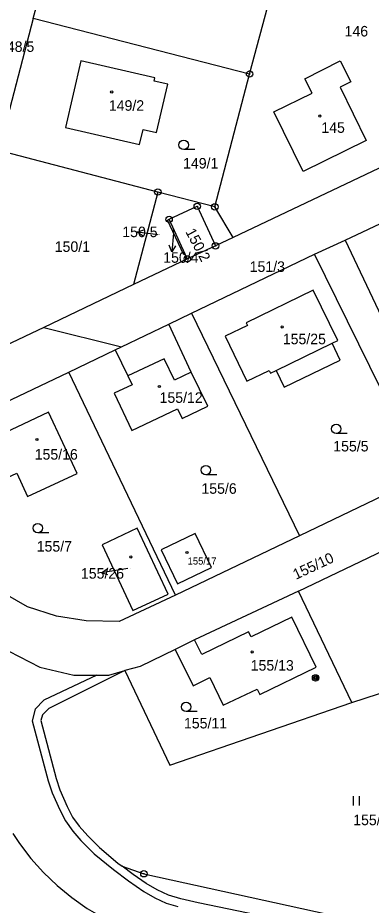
# Model space of a CAD drawing. Extents: x -737240 to -735272, y -1119606 to -1117878.
# Drawn here: x -736818.9 to -736761.9, y -1119214.7 to -1119071.3 of the extents above; entities that cross this region are included whole.
import ezdxf

# ---------------------------------------------------------------- set-up
doc = ezdxf.new("R2010")
doc.units = 0
for name, color, linetype in [('Level 1', 7, 'Continuous'), ('Level 16', 7, 'Continuous'), ('Level 18', 7, 'Continuous'), ('Level 19', 7, 'Continuous'), ('Level 25', 7, 'Continuous'), ('Level 4', 7, 'Continuous')]:
    doc.layers.add(name, color=color, linetype=linetype)

msp = doc.modelspace()

# ---------------------------------------------------------------- linework, layer by layer
at = {"layer": 'Level 1'}
for p, q in [((-736816.39, -1119071.39), (-736810.93, -1119050.62)), ((-736781.48, -1119080.38), (-736775.91, -1119059.43)), ((-736816.39, -1119071.39), (-736822, -1119092.75)), ((-736781.48, -1119080.38), (-736816.39, -1119071.39)), ((-736787.09, -1119101.84), (-736781.48, -1119080.38)), ((-736796.29, -1119099.44), (-736822, -1119092.75)), ((-736757.34, -1119094.04), (-736784.14, -1119106.77)), ((-736796.29, -1119099.44), (-736800.2, -1119114.37)), ((-736787.09, -1119101.84), (-736796.29, -1119099.44)), ((-736784.14, -1119106.77), (-736787.09, -1119101.84)), ((-736766.08, -1119107.23), (-736755.89, -1119102.38)), ((-736791.87, -1119109.47), (-736794.47, -1119103.84)), ((-736784.14, -1119106.77), (-736786.98, -1119108.14)), ((-736771.02, -1119109.49), (-736766.08, -1119107.23)), ((-736786.98, -1119108.14), (-736791.52, -1119110.23)), ((-736791.52, -1119110.23), (-736800.2, -1119114.37)), ((-736791.52, -1119110.23), (-736791.87, -1119109.47)), ((-736790.84, -1119119), (-736771.02, -1119109.49)), ((-736753.41, -1119145.33), (-736771.02, -1119109.49)), ((-736800.2, -1119114.37), (-736814.71, -1119121.3)), ((-736794.53, -1119120.77), (-736790.84, -1119119)), ((-736790.84, -1119119), (-736773.44, -1119154.96)), ((-736814.71, -1119121.3), (-736802.17, -1119124.44)), ((-736802.17, -1119124.44), (-736794.53, -1119120.77)), ((-736790.92, -1119128.54), (-736794.53, -1119120.77)), ((-736803.16, -1119124.91), (-736802.17, -1119124.44)), ((-736810.68, -1119128.52), (-736803.16, -1119124.91)), ((-736803.16, -1119124.91), (-736801.14, -1119129.12)), ((-736830.54, -1119138.05), (-736810.68, -1119128.52)), ((-736793.45, -1119164.56), (-736810.68, -1119128.52)), ((-736753.41, -1119145.33), (-736773.44, -1119154.96)), ((-736773.6, -1119163.92), (-736752.44, -1119153.75)), ((-736773.44, -1119154.96), (-736793.45, -1119164.56)), ((-736773.6, -1119163.92), (-736790.36, -1119171.8)), ((-736764.96, -1119181.9), (-736773.6, -1119163.92)), ((-736790.36, -1119171.8), (-736793.49, -1119173.32)), ((-736764.96, -1119181.9), (-736735.36, -1119172.13))]:
    msp.add_line(p, q, dxfattribs=at)
for points in [[(-736808.72, -1119078.23), (-736811.19, -1119089.04), (-736799.24, -1119091.78), (-736798.67, -1119089.34), (-736796.48, -1119089.85), (-736794.69, -1119082.04), (-736796.89, -1119081.54), (-736796.76, -1119080.97), (-736808.72, -1119078.23)], [(-736772.57, -1119081.15), (-736766.86, -1119078.25), (-736765.15, -1119081.63), (-736766.89, -1119082.5), (-736762.66, -1119091.11), (-736772.86, -1119096.14), (-736777.56, -1119086.49), (-736771.41, -1119083.45), (-736772.57, -1119081.15)], [(-736794.47, -1119103.84), (-736789.93, -1119101.74), (-736786.98, -1119108.14)], [(-736791.87, -1119109.47), (-736792.1, -1119109.58), (-736794.72, -1119104.01), (-736794.47, -1119103.84)], [(-736766.08, -1119107.23), (-736754.84, -1119130.95), (-736746.47, -1119126.97), (-736739.42, -1119123.41), (-736740.88, -1119120.36), (-736741.59, -1119118.86), (-736740.94, -1119118.55), (-736741.1, -1119118.23), (-736743.04, -1119119.15), (-736744.61, -1119115.84)], [(-736768.18, -1119123.88), (-736767.26, -1119123.44), (-736771.23, -1119115.28), (-736782.06, -1119120.55), (-736781.84, -1119121), (-736785.44, -1119122.75), (-736781.92, -1119130), (-736778.33, -1119128.26), (-736778.11, -1119128.71), (-736777.21, -1119128.27)], [(-736814.71, -1119121.3), (-736826.19, -1119126.79), (-736829.11, -1119119.8)], [(-736777.21, -1119128.27), (-736775.88, -1119130.97), (-736766.88, -1119126.58), (-736768.18, -1119123.88)], [(-736801.14, -1119129.12), (-736800.45, -1119130.57), (-736803.35, -1119131.96), (-736800.46, -1119137.97), (-736793.13, -1119134.45), (-736792.37, -1119136.04), (-736788.24, -1119134.06), (-736790.92, -1119128.54)], [(-736813.95, -1119135.03), (-736824.1, -1119139.8), (-736821.24, -1119145.87), (-736819.07, -1119144.88), (-736817.3, -1119148.63), (-736809.3, -1119144.91), (-736813.95, -1119135.03)], [(-736793.45, -1119164.56), (-736802.54, -1119168.8), (-736807.84, -1119168.73), (-736812.66, -1119167.94), (-736817.35, -1119166.45), (-736822.33, -1119163.61), (-736830.54, -1119138.05)], [(-736834.17, -1119146.38), (-736828.05, -1119165.45), (-736824.63, -1119169.96), (-736820.34, -1119173.62), (-736815.31, -1119176.18), (-736809.83, -1119177.49), (-736806.12, -1119177.49)], [(-736805.29, -1119156.42), (-736800.3, -1119167.06), (-736794.61, -1119164.38), (-736799.62, -1119153.76), (-736805.29, -1119156.42)], [(-736793.11, -1119162.73), (-736787.61, -1119160.11), (-736790.24, -1119154.61), (-736795.73, -1119157.24), (-736793.11, -1119162.73)], [(-736793.49, -1119173.32), (-736790.57, -1119179.2), (-736787.89, -1119177.87), (-736785.76, -1119182.34), (-736780.28, -1119179.73), (-736779.85, -1119180.62), (-736770.75, -1119176.22), (-736774.67, -1119168.13), (-736781.25, -1119171.32), (-736781.65, -1119170.49), (-736789.21, -1119174.17), (-736790.36, -1119171.8)], [(-736793.49, -1119173.32), (-736799.15, -1119176.07), (-736801.59, -1119176.75)], [(-736806.12, -1119177.49), (-736814.68, -1119181.53), (-736816.07, -1119182.96), (-736816.58, -1119184.86), (-736814, -1119194.58), (-736813.35, -1119196.48), (-736812.12, -1119199.27), (-736811.19, -1119201.05), (-736810.03, -1119202.71), (-736808.71, -1119204.22), (-736806.57, -1119206.33), (-736803.45, -1119208.91), (-736801.05, -1119210.74), (-736798.54, -1119212.46), (-736796.78, -1119213.47), (-736794.97, -1119214.3), (-736793.05, -1119214.87)], [(-736801.59, -1119176.75), (-736813.89, -1119182.87), (-736814.9, -1119183.88), (-736815.18, -1119184.84), (-736812.71, -1119194.2), (-736812.12, -1119196.03), (-736810.94, -1119198.72), (-736810.05, -1119200.41), (-736809, -1119201.89), (-736807.61, -1119203.44), (-736805.7, -1119205.33), (-736802.73, -1119207.84), (-736802.05, -1119208.36)], [(-736806.12, -1119177.49), (-736804.18, -1119177.49), (-736801.59, -1119176.75)], [(-736801.59, -1119176.75), (-736794.33, -1119192.04), (-736764.96, -1119181.9)], [(-736819.7, -1119203.08), (-736818.63, -1119204.71), (-736816.77, -1119207.12), (-736814.73, -1119209.38), (-736812.53, -1119211.48), (-736810.18, -1119213.41), (-736807.69, -1119215.17), (-736805.07, -1119216.72), (-736802.35, -1119218.08), (-736799.53, -1119219.23), (-736796.64, -1119220.17), (-736793.68, -1119220.89), (-736773.1, -1119225.22)], [(-736802.05, -1119208.36), (-736798.54, -1119209.58), (-736743.15, -1119221.74)], [(-736668.11, -1119254.91), (-736668.26, -1119254.47), (-736670.65, -1119252.61), (-736672.34, -1119251.49), (-736674.09, -1119250.44), (-736675.92, -1119249.53), (-736724.83, -1119229.75), (-736740.44, -1119225.23), (-736766.11, -1119219.16), (-736789.8, -1119214.25), (-736792.59, -1119213.62), (-736794.57, -1119213.03), (-736796.41, -1119212.17), (-736798.16, -1119211.14), (-736800.29, -1119209.7), (-736802.05, -1119208.36)]]:
    msp.add_lwpolyline(points, dxfattribs=at)
at = {"layer": 'Level 16'}
for points in [[(-736798.677, -1119106.562), (-736799.606, -1119105.939), (-736798.55, -1119105.57)], [(-736796.33, -1119106.36), (-736796.63, -1119106.32), (-736799.606, -1119105.939)], [(-736793.91, -1119105.48), (-736793.78, -1119106.09), (-736794.018, -1119109.081)], [(-736793.44, -1119108.123), (-736794.018, -1119109.081), (-736794.437, -1119108.044)], [(-736801.14, -1119160.28), (-736802.44, -1119160.48), (-736805.405, -1119160.936)], [(-736804.341, -1119161.278), (-736805.405, -1119160.936), (-736804.493, -1119160.29)]]:
    msp.add_lwpolyline(points, dxfattribs=at)
at = {"layer": 'Level 25'}
for p, q in [((-736790.338, -1119092.58), (-736792.12, -1119092.58)), ((-736765.718, -1119138.46), (-736767.5, -1119138.46)), ((-736786.758, -1119145.11), (-736788.54, -1119145.11)), ((-736813.878, -1119154.48), (-736815.66, -1119154.48)), ((-736789.948, -1119183.37), (-736791.73, -1119183.37)), ((-736764.787, -1119197.055), (-736764.787, -1119198.555)), ((-736763.765, -1119198.555), (-736763.765, -1119197.055))]:
    msp.add_line(p, q, dxfattribs=at)
for centre, major_axis, ratio in [((-736781.48, -1119080.38), (0.516, 0), 0.9848078), ((-736781.48, -1119080.38), (0.0375, 0), 0.9848078), ((-736803.73, -1119083.28), (0.18, 0), 0.9848078), ((-736770.14, -1119087.16), (0.18, 0), 0.9848078), ((-736792.12, -1119091.824), (0.764, 0), 0.9894236), ((-736796.29, -1119099.44), (0.516, 0), 0.9848078), ((-736796.29, -1119099.44), (0.0375, 0), 0.9848078), ((-736789.93, -1119101.74), (0.516, 0), 0.9848078), ((-736787.09, -1119101.84), (0.516, 0), 0.9848078), ((-736789.93, -1119101.74), (0.0375, 0), 0.9848078), ((-736787.09, -1119101.84), (0.0375, 0), 0.9848078), ((-736794.47, -1119103.84), (0.516, 0), 0.9848078), ((-736794.47, -1119103.84), (0.0375, 0), 0.9848078), ((-736786.98, -1119108.14), (0.516, 0), 0.9848078), ((-736786.98, -1119108.14), (0.0375, 0), 0.9848078), ((-736791.52, -1119110.23), (0.516, 0), 0.9848078), ((-736791.52, -1119110.23), (0.0375, 0), 0.9848078), ((-736776.23, -1119121.24), (0.18, 0), 0.9848078), ((-736796.03, -1119130.85), (0.18, 0), 0.9848078), ((-736767.5, -1119137.704), (0.764, 0), 0.9894236), ((-736815.81, -1119139.42), (0.18, 0), 0.9848078), ((-736788.54, -1119144.354), (0.764, 0), 0.9894236), ((-736815.66, -1119153.724), (0.764, 0), 0.9894236), ((-736791.59, -1119157.68), (0.18, 0), 0.9848078), ((-736800.65, -1119158.4), (0.18, 0), 0.9848078), ((-736781.06, -1119173.74), (0.18, 0), 0.9848078), ((-736770.83, -1119177.93), (0.516, 0), 0.9848078), ((-736770.83, -1119177.93), (0.309, 0), 0.9848078), ((-736770.83, -1119177.93), (0.155, 0), 0.9848078), ((-736791.73, -1119182.614), (0.764, 0), 0.9894236), ((-736798.54, -1119209.58), (0.516, 0), 0.9848078), ((-736798.54, -1119209.58), (0.0375, 0), 0.9848078)]:
    msp.add_ellipse(centre, major_axis=major_axis, ratio=ratio, dxfattribs=at)
at = {"layer": 'Level 4'}
msp.add_line((-736777.21, -1119128.27), (-736768.18, -1119123.88), dxfattribs=at)
msp.add_lwpolyline([(-736790.92, -1119128.54), (-736793.62, -1119129.84), (-736795.29, -1119126.37), (-736801.14, -1119129.12)], dxfattribs=at)

# ---------------------------------------------------------------- texts
at = {"layer": 'Level 16'}
for s, p in [('148/5', (-736821.92, -1119076.8)), ('150/5', (-736802.025, -1119106.73)), ('150/4', (-736795.415, -1119110.87)), ('155/26', (-736808.7, -1119161.9))]:
    msp.add_text(s, height=1.7, dxfattribs=at).set_placement(p)
at = {"layer": 'Level 18'}
for s, height, p in [('146', 1.7, (-736766.145, -1119074.31)), ('149/1', 1.7, (-736792.215, -1119095.64)), ('150/1', 1.7, (-736812.925, -1119109.11)), ('150/5', 0.1, (-736796.33, -1119106.36)), ('151/3', 1.7, (-736781.465, -1119112.34)), ('155/5', 1.7, (-736767.975, -1119141.35)), ('155/6', 1.7, (-736789.255, -1119148.19)), ('155/7', 1.7, (-736815.835, -1119157.53)), ('155/11', 1.7, (-736792.07, -1119186.1)), ('155/1', 1.7, (-736764.755, -1119201.73))]:
    msp.add_text(s, height=height, dxfattribs=at).set_placement(p)
for s, height, rotation, p in [('150/4', 0.1, 296.91324, (-736793.91, -1119105.48)), ('150/2', 1.7, 297.9603, (-736791.884, -1119105.847)), ('155/10', 1.7, 25.19649, (-736774, -1119162.1))]:
    msp.add_text(s, height=height, rotation=rotation, dxfattribs=at).set_placement(p)
at = {"layer": 'Level 19'}
for s, height, p in [('149/2', 1.7, (-736804.19, -1119086.31)), ('145', 1.7, (-736769.9, -1119089.88)), ('155/25', 1.7, (-736776.12, -1119124.03)), ('155/12', 1.7, (-736796.005, -1119133.5)), ('155/16', 1.7, (-736816.16, -1119142.67)), ('155/17', 1.14, (-736791.485, -1119159.62)), ('155/26', 0.1, (-736800.965, -1119160.28)), ('155/13', 1.7, (-736781.305, -1119176.76))]:
    msp.add_text(s, height=height, dxfattribs=at).set_placement(p)

doc.saveas('drawing.dxf')
